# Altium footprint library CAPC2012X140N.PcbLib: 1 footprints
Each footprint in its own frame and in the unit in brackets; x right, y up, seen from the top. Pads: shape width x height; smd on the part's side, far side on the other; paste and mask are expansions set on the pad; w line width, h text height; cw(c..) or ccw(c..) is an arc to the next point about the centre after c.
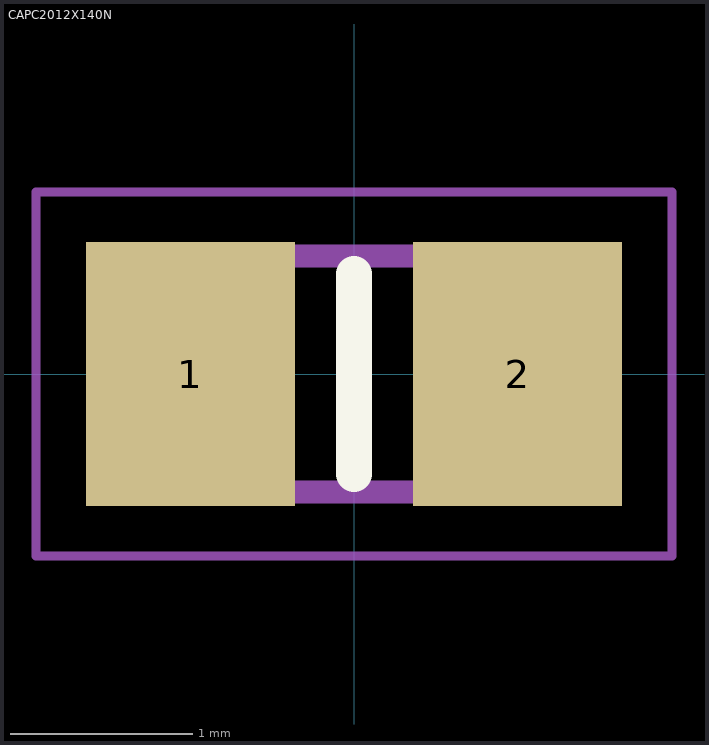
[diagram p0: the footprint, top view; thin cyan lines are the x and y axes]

## CAPC2012X140N [mm]
pads (2):
  rect 1.15x1.45 smd: 1(-0.9,0) 2(0.9,0)
Top Overlay:
  lines w0.2: 0,-0.55 0,0.55
Assembly Top:
  region: 1,-0.65 0.5,-0.65 0.5,0.65 1,0.65
  region: -0.5,-0.65 -1,-0.65 -1,0.65 -0.5,0.65
  lines w0.127: -1,-0.65 -1,0.65 1,0.65 1,-0.65 -1,-0.65
Courtyard Top:
  lines w0.05: -1.75,-1 -1.75,1 1.75,1 1.75,-1 -1.75,-1
3D body "step_temp.STEP": height 0.94, standoff 0, extent -1.005,-0.625 1.005,0.625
